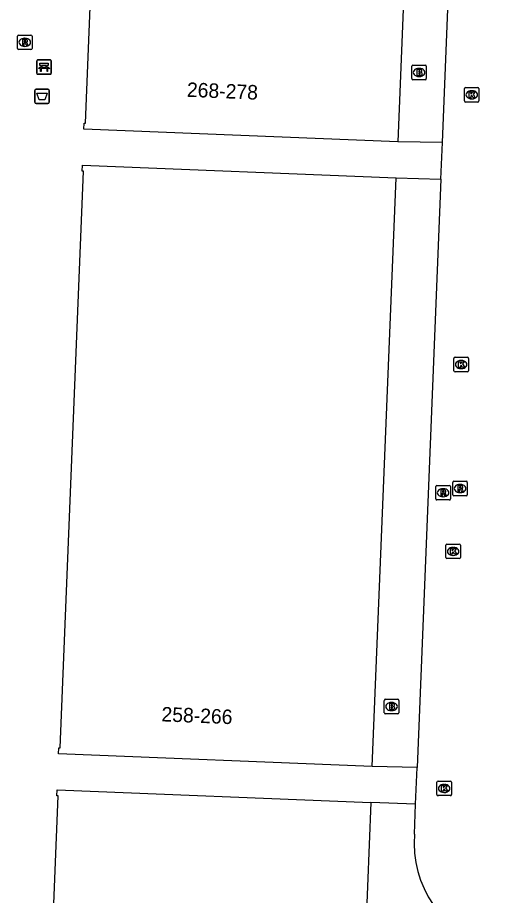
# Model space of a CAD drawing. Extents: x 160891 to 161384, y 386490 to 386907.
# Drawn here: x 161189.7 to 161223.2, y 386595.4 to 386656.1 of the extents above; entities that cross this region are included whole.
import ezdxf

# ---------------------------------------------------------------- set-up
doc = ezdxf.new("R2010")
doc.units = 0
for name, color, linetype in [('IMGEO_Afvalbak', 7, 'Continuous'), ('IMGEO_Bank', 7, 'Continuous'), ('IMGEO_Brandkraan', 7, 'Continuous'), ('IMGEO_Kolk', 7, 'Continuous'), ('IMGEO_Pand', 7, 'Continuous'), ('IMGEO_Pand_nummerreeks', 7, 'Continuous'), ('IMGEO_Rijbaan_lokaal_open', 7, 'Continuous'), ('IMGEO_Rioolput', 7, 'Continuous'), ('IMGEO_Voetgangersgebied_open', 7, 'Continuous'), ('IMGEO_Voetpad_open', 7, 'Continuous')]:
    doc.layers.add(name, color=color, linetype=linetype)

msp = doc.modelspace()

# ---------------------------------------------------------------- linework, layer by layer
at = {"layer": 'IMGEO_Afvalbak'}
for p, q in [((161190.919, 386650.214), (161190.919, 386651.014)), ((161190.919, 386651.014), (161190.919, 386650.214)), ((161191.019, 386651.114), (161191.809, 386651.114)), ((161191.809, 386651.114), (161191.019, 386651.114)), ((161191.909, 386651.014), (161191.909, 386650.214)), ((161191.909, 386650.214), (161191.909, 386651.014)), ((161191.809, 386650.114), (161191.019, 386650.114)), ((161191.019, 386650.114), (161191.809, 386650.114))]:
    msp.add_line(p, q, dxfattribs=at)
msp.add_lwpolyline([(161191.062, 386650.828), (161191.766, 386650.828), (161191.617, 386650.358), (161191.211, 386650.358), (161191.062, 386650.828)], dxfattribs=at)
for centre, start, end in [((161191.019, 386651.014), 90, 180), ((161191.019, 386651.014), 90, 180), ((161191.809, 386651.014), 0, 90), ((161191.809, 386651.014), 360, 90), ((161191.019, 386650.214), 180, 270), ((161191.019, 386650.214), 180, 270), ((161191.809, 386650.214), 270, 0), ((161191.809, 386650.214), 270, 0)]:
    msp.add_arc(centre, 0.1, start, end, dxfattribs=at)
at = {"layer": 'IMGEO_Bank'}
for p, q in [((161191.058, 386652.204), (161191.058, 386653.045)), ((161191.058, 386653.045), (161191.058, 386652.204)), ((161191.133, 386653.129), (161191.974, 386653.129)), ((161191.974, 386653.129), (161191.133, 386653.129)), ((161192.058, 386653.054), (161192.058, 386652.213)), ((161192.058, 386652.213), (161192.058, 386653.054)), ((161191.755, 386652.527), (161191.362, 386652.527)), ((161191.367, 386652.635), (161191.367, 386652.741)), ((161191.411, 386652.741), (161191.411, 386652.635)), ((161191.699, 386652.747), (161191.417, 386652.747)), ((161191.417, 386652.629), (161191.699, 386652.629)), ((161191.705, 386652.635), (161191.705, 386652.741)), ((161191.749, 386652.741), (161191.749, 386652.635)), ((161191.983, 386652.129), (161191.142, 386652.129)), ((161191.142, 386652.129), (161191.983, 386652.129))]:
    msp.add_line(p, q, dxfattribs=at)
for points in [[(161191.361, 386652.747), (161191.275, 386652.747), (161191.275, 386652.908), (161191.838, 386652.908), (161191.838, 386652.747), (161191.755, 386652.747)], [(161191.305, 386652.527), (161191.163, 386652.527), (161191.275, 386652.629), (161191.361, 386652.629)], [(161191.355, 386652.52), (161191.355, 386652.313), (161191.312, 386652.313), (161191.312, 386652.52)], [(161191.755, 386652.629), (161191.838, 386652.629), (161191.95, 386652.527), (161191.811, 386652.527)], [(161191.805, 386652.52), (161191.805, 386652.313), (161191.761, 386652.313), (161191.761, 386652.52)]]:
    msp.add_lwpolyline(points, dxfattribs=at)
for centre, radius, start, end in [((161191.136, 386653.051), 0.0779, 92.4484, 184.28452), ((161191.136, 386653.051), 0.0779, 92.4484, 184.28452), ((161191.98, 386653.051), 0.0779, 2.4484, 94.28452), ((161191.98, 386653.051), 0.0779, 2.4484, 94.28452), ((161191.136, 386652.207), 0.0779, 182.4484, 274.28452), ((161191.136, 386652.207), 0.0779, 182.4484, 274.28452), ((161191.305, 386652.52), 0.00671, 2.89567, 87.10433), ((161191.362, 386652.52), 0.00671, 92.89567, 177.10433), ((161191.36, 386652.74), 0.00671, 2.89567, 87.10433), ((161191.36, 386652.636), 0.00671, 272.89567, 357.10433), ((161191.417, 386652.74), 0.00671, 92.89567, 177.10433), ((161191.417, 386652.636), 0.00671, 182.89567, 267.10433), ((161191.699, 386652.74), 0.00671, 2.89567, 87.10433), ((161191.699, 386652.636), 0.00671, 272.89567, 357.10433), ((161191.756, 386652.74), 0.00671, 92.89567, 177.10433), ((161191.756, 386652.636), 0.00671, 182.89567, 267.10433), ((161191.754, 386652.52), 0.00671, 2.89567, 87.10433), ((161191.811, 386652.52), 0.00671, 92.89567, 177.10433), ((161191.98, 386652.207), 0.0779, 272.4484, 4.28452), ((161191.98, 386652.207), 0.0779, 272.4484, 4.28452)]:
    msp.add_arc(centre, radius, start, end, dxfattribs=at)
at = {"layer": 'IMGEO_Brandkraan'}
for p, q in [((161216.976, 386651.833), (161216.976, 386652.685)), ((161217.051, 386652.759), (161217.903, 386652.759)), ((161217.464, 386652.539), (161217.489, 386652.539)), ((161217.977, 386652.685), (161217.977, 386651.833)), ((161217.903, 386651.759), (161217.051, 386651.759)), ((161217.487, 386651.979), (161217.462, 386651.979)), ((161215.075, 386608.011), (161215.075, 386608.863)), ((161215.15, 386608.937), (161216.002, 386608.937)), ((161215.563, 386608.717), (161215.588, 386608.717)), ((161216.076, 386608.863), (161216.076, 386608.011)), ((161216.002, 386607.937), (161215.15, 386607.937)), ((161215.586, 386608.157), (161215.561, 386608.157))]:
    msp.add_line(p, q, dxfattribs=at)
for points in [[(161216.976, 386651.833), (161216.976, 386652.685)], [(161217.051, 386652.759), (161217.903, 386652.759)], [(161217.324, 386652.459), (161217.324, 386652.059), (161217.537, 386652.059)], [(161217.555, 386652.459), (161217.324, 386652.459)], [(161217.503, 386652.378), (161217.449, 386652.378), (161217.449, 386652.302)], [(161217.449, 386652.302), (161217.502, 386652.302)], [(161217.511, 386652.226), (161217.449, 386652.226), (161217.449, 386652.145)], [(161217.977, 386652.685), (161217.977, 386651.833)], [(161217.903, 386651.759), (161217.051, 386651.759)], [(161217.449, 386652.145), (161217.511, 386652.145)], [(161215.075, 386608.011), (161215.075, 386608.863)], [(161215.15, 386608.937), (161216.002, 386608.937)], [(161215.423, 386608.637), (161215.423, 386608.237), (161215.636, 386608.237)], [(161215.654, 386608.637), (161215.423, 386608.637)], [(161215.602, 386608.556), (161215.548, 386608.556), (161215.548, 386608.48)], [(161216.076, 386608.863), (161216.076, 386608.011)], [(161216.002, 386607.937), (161215.15, 386607.937)], [(161215.548, 386608.48), (161215.601, 386608.48)], [(161215.61, 386608.404), (161215.548, 386608.404), (161215.548, 386608.323)], [(161215.548, 386608.323), (161215.61, 386608.323)]]:
    msp.add_lwpolyline(points, dxfattribs=at)
for centre, radius, start, end in [((161217.053, 386652.683), 0.0765, 91.55205, 178.44795), ((161217.053, 386652.683), 0.0765, 91.55205, 178.44795), ((161217.504, 386652.34), 0.0379, 267.82845, 90.93552), ((161217.512, 386652.185), 0.0404, 269.87594, 90.50774), ((161217.559, 386652.314), 0.145, 59.4692, 91.53667), ((161217.584, 386652.361), 0.0922, 285.51372, 58.15012), ((161217.589, 386652.169), 0.105, 301.31148, 78.98903), ((161217.901, 386652.683), 0.0765, 1.55205, 88.44795), ((161217.901, 386652.683), 0.0765, 1.55205, 88.44795), ((161217.053, 386651.835), 0.0765, 181.55205, 268.44795), ((161217.053, 386651.835), 0.0765, 181.55205, 268.44795), ((161217.543, 386652.31), 0.251, 268.66757, 293.53466), ((161217.901, 386651.835), 0.0765, 271.55205, 358.44795), ((161217.901, 386651.835), 0.0765, 271.55205, 358.44795), ((161215.152, 386608.861), 0.0765, 91.55205, 178.44795), ((161215.152, 386608.861), 0.0765, 91.55205, 178.44795), ((161215.603, 386608.518), 0.0379, 267.82845, 90.93552), ((161215.658, 386608.492), 0.145, 59.4692, 91.53667), ((161215.683, 386608.539), 0.0922, 285.51372, 58.15012), ((161216, 386608.861), 0.0765, 1.55205, 88.44795), ((161216, 386608.861), 0.0765, 1.55205, 88.44795), ((161215.152, 386608.013), 0.0765, 181.55205, 268.44795), ((161215.152, 386608.013), 0.0765, 181.55205, 268.44795), ((161215.611, 386608.363), 0.0404, 269.87594, 90.50774), ((161215.642, 386608.488), 0.251, 268.66757, 293.53466), ((161215.688, 386608.347), 0.105, 301.31148, 78.98903), ((161216, 386608.013), 0.0765, 271.55205, 358.44795), ((161216, 386608.013), 0.0765, 271.55205, 358.44795)]:
    msp.add_arc(centre, radius, start, end, dxfattribs=at)
for centre, major_axis, ratio, start_param, end_param in [((161217.463, 386652.259), (-0.387, 0.002), 0.722429, 4.712389, 7.853982), ((161217.488, 386652.259), (-0.39, 0.002), 0.717154, 1.570796, 4.712389), ((161215.562, 386608.437), (-0.387, 0.002), 0.722429, 4.712389, 7.853982), ((161215.587, 386608.437), (-0.39, 0.002), 0.717154, 1.570796, 4.712389)]:
    msp.add_ellipse(centre, major_axis=major_axis, ratio=ratio, start_param=start_param, end_param=end_param, dxfattribs=at)
at = {"layer": 'IMGEO_Kolk'}
for p, q in [((161220.615, 386650.288), (161220.615, 386651.14)), ((161220.69, 386651.214), (161221.542, 386651.214)), ((161221.103, 386650.994), (161221.128, 386650.994)), ((161221.616, 386651.14), (161221.616, 386650.288)), ((161221.126, 386650.434), (161221.101, 386650.434)), ((161221.542, 386650.214), (161220.69, 386650.214)), ((161219.886, 386631.645), (161219.886, 386632.497)), ((161219.961, 386632.571), (161220.813, 386632.571)), ((161220.374, 386632.351), (161220.399, 386632.351)), ((161220.887, 386632.497), (161220.887, 386631.645)), ((161220.813, 386631.571), (161219.961, 386631.571)), ((161220.397, 386631.791), (161220.372, 386631.791)), ((161219.331, 386618.732), (161219.331, 386619.584)), ((161219.406, 386619.658), (161220.258, 386619.658)), ((161219.819, 386619.438), (161219.844, 386619.438)), ((161220.332, 386619.584), (161220.332, 386618.732)), ((161219.842, 386618.878), (161219.817, 386618.878)), ((161220.258, 386618.658), (161219.406, 386618.658)), ((161218.71, 386602.352), (161218.71, 386603.204)), ((161218.785, 386603.278), (161219.637, 386603.278)), ((161219.198, 386603.058), (161219.223, 386603.058)), ((161219.711, 386603.204), (161219.711, 386602.352)), ((161219.221, 386602.498), (161219.196, 386602.498)), ((161219.637, 386602.278), (161218.785, 386602.278))]:
    msp.add_line(p, q, dxfattribs=at)
for points in [[(161220.615, 386650.288), (161220.615, 386651.14)], [(161220.69, 386651.214), (161221.542, 386651.214)], [(161221.616, 386651.14), (161221.616, 386650.288)], [(161220.936, 386650.914), (161221.059, 386650.914), (161221.059, 386650.763), (161221.189, 386650.914), (161221.353, 386650.914), (161221.207, 386650.763), (161221.36, 386650.514), (161221.208, 386650.514), (161221.123, 386650.678), (161221.059, 386650.611), (161221.059, 386650.514), (161220.936, 386650.514), (161220.936, 386650.914)], [(161221.542, 386650.214), (161220.69, 386650.214)], [(161219.886, 386631.645), (161219.886, 386632.497)], [(161219.961, 386632.571), (161220.813, 386632.571)], [(161220.207, 386632.271), (161220.33, 386632.271), (161220.33, 386632.12), (161220.46, 386632.271), (161220.624, 386632.271), (161220.478, 386632.12), (161220.631, 386631.871), (161220.479, 386631.871), (161220.394, 386632.035), (161220.33, 386631.968), (161220.33, 386631.871), (161220.207, 386631.871), (161220.207, 386632.271)], [(161220.887, 386632.497), (161220.887, 386631.645)], [(161220.813, 386631.571), (161219.961, 386631.571)], [(161219.331, 386618.732), (161219.331, 386619.584)], [(161219.406, 386619.658), (161220.258, 386619.658)], [(161220.332, 386619.584), (161220.332, 386618.732)], [(161219.652, 386619.358), (161219.775, 386619.358), (161219.775, 386619.207), (161219.905, 386619.358), (161220.069, 386619.358), (161219.923, 386619.207), (161220.076, 386618.958), (161219.924, 386618.958), (161219.839, 386619.122), (161219.775, 386619.055), (161219.775, 386618.958), (161219.652, 386618.958), (161219.652, 386619.358)], [(161220.258, 386618.658), (161219.406, 386618.658)], [(161218.71, 386602.352), (161218.71, 386603.204)], [(161218.785, 386603.278), (161219.637, 386603.278)], [(161219.711, 386603.204), (161219.711, 386602.352)], [(161219.031, 386602.978), (161219.154, 386602.978), (161219.154, 386602.827), (161219.284, 386602.978), (161219.448, 386602.978), (161219.302, 386602.827), (161219.455, 386602.578), (161219.303, 386602.578), (161219.218, 386602.742), (161219.154, 386602.675), (161219.154, 386602.578), (161219.031, 386602.578), (161219.031, 386602.978)], [(161219.637, 386602.278), (161218.785, 386602.278)]]:
    msp.add_lwpolyline(points, dxfattribs=at)
for centre, start, end in [((161220.692, 386651.138), 91.55205, 178.44795), ((161220.692, 386651.138), 91.55205, 178.44795), ((161221.54, 386651.138), 1.55205, 88.44795), ((161221.54, 386651.138), 1.55205, 88.44795), ((161220.692, 386650.29), 181.55205, 268.44795), ((161220.692, 386650.29), 181.55205, 268.44795), ((161221.54, 386650.29), 271.55205, 358.44795), ((161221.54, 386650.29), 271.55205, 358.44795), ((161219.963, 386632.495), 91.55205, 178.44795), ((161219.963, 386632.495), 91.55205, 178.44795), ((161220.811, 386632.495), 1.55205, 88.44795), ((161220.811, 386632.495), 1.55205, 88.44795), ((161219.963, 386631.647), 181.55205, 268.44795), ((161219.963, 386631.647), 181.55205, 268.44795), ((161220.811, 386631.647), 271.55205, 358.44795), ((161220.811, 386631.647), 271.55205, 358.44795), ((161219.408, 386619.582), 91.55205, 178.44795), ((161219.408, 386619.582), 91.55205, 178.44795), ((161220.256, 386619.582), 1.55205, 88.44795), ((161220.256, 386619.582), 1.55205, 88.44795), ((161219.408, 386618.734), 181.55205, 268.44795), ((161219.408, 386618.734), 181.55205, 268.44795), ((161220.256, 386618.734), 271.55205, 358.44795), ((161220.256, 386618.734), 271.55205, 358.44795), ((161218.787, 386603.202), 91.55205, 178.44795), ((161218.787, 386603.202), 91.55205, 178.44795), ((161219.635, 386603.202), 1.55205, 88.44795), ((161219.635, 386603.202), 1.55205, 88.44795), ((161218.787, 386602.354), 181.55205, 268.44795), ((161218.787, 386602.354), 181.55205, 268.44795), ((161219.635, 386602.354), 271.55205, 358.44795), ((161219.635, 386602.354), 271.55205, 358.44795)]:
    msp.add_arc(centre, 0.0765, start, end, dxfattribs=at)
for centre, major_axis, ratio, start_param, end_param in [((161221.102, 386650.714), (-0.387, 0.002), 0.722429, 4.712389, 7.853982), ((161221.127, 386650.714), (-0.39, 0.002), 0.717154, 1.570796, 4.712389), ((161220.373, 386632.071), (-0.387, 0.002), 0.722429, 4.712389, 7.853982), ((161220.398, 386632.071), (-0.39, 0.002), 0.717154, 1.570796, 4.712389), ((161219.818, 386619.158), (-0.387, 0.002), 0.722429, 4.712389, 7.853982), ((161219.843, 386619.158), (-0.39, 0.002), 0.717154, 1.570796, 4.712389), ((161219.197, 386602.778), (-0.387, 0.002), 0.722429, 4.712389, 7.853982), ((161219.222, 386602.778), (-0.39, 0.002), 0.717154, 1.570796, 4.712389)]:
    msp.add_ellipse(centre, major_axis=major_axis, ratio=ratio, start_param=start_param, end_param=end_param, dxfattribs=at)
at = {"layer": 'IMGEO_Pand'}
for points in [[(161216.005, 386647.458), (161194.302, 386648.347), (161194.32, 386648.757), (161194.42, 386648.752), (161196.801, 386707.775)], [(161214.777, 386707.152), (161234.482, 386694.929), (161234.896, 386694.91), (161234.274, 386679.434), (161217.32, 386680.124), (161216.005, 386647.458)], [(161214.242, 386604.304), (161192.56, 386605.179), (161192.572, 386605.592), (161192.672, 386605.589), (161194.288, 386645.43), (161194.188, 386645.434), (161194.205, 386645.849), (161215.889, 386644.972)], [(161214.242, 386604.304), (161215.889, 386644.972)], [(161191.198, 386569.006), (161192.541, 386602.265), (161192.441, 386602.269), (161192.456, 386602.678), (161214.141, 386601.806)], [(161214.141, 386601.806), (161213.556, 386587.296)]]:
    msp.add_lwpolyline(points, dxfattribs=at)
at = {"layer": 'IMGEO_Rijbaan_lokaal_open'}
for points in [[(161219.091, 386647.411), (161219.977, 386669.302)], [(161218.989, 386644.89), (161219.091, 386647.411)], [(161218.989, 386644.89), (161217.342, 386604.22)], [(161217.24, 386601.701), (161217.342, 386604.22)], [(161217.156, 386599.626), (161217.24, 386601.701)]]:
    msp.add_lwpolyline(points, dxfattribs=at)
msp.add_arc((161224.629, 386599.004), 7.499, 175.24232, 253.73554, dxfattribs=at)
at = {"layer": 'IMGEO_Rioolput'}
for p, q in [((161189.724, 386653.917), (161189.724, 386654.769)), ((161189.799, 386654.843), (161190.651, 386654.843)), ((161190.212, 386654.623), (161190.237, 386654.623)), ((161190.725, 386654.769), (161190.725, 386653.917)), ((161190.235, 386654.063), (161190.21, 386654.063)), ((161190.651, 386653.843), (161189.799, 386653.843)), ((161218.711, 386623.712), (161219.563, 386623.712)), ((161219.81, 386623.079), (161219.81, 386623.931)), ((161219.885, 386624.005), (161220.737, 386624.005)), ((161220.298, 386623.785), (161220.323, 386623.785)), ((161220.811, 386623.931), (161220.811, 386623.079)), ((161218.636, 386622.786), (161218.636, 386623.638)), ((161219.124, 386623.492), (161219.149, 386623.492)), ((161219.637, 386623.638), (161219.637, 386622.786)), ((161220.321, 386623.225), (161220.296, 386623.225)), ((161219.563, 386622.712), (161218.711, 386622.712)), ((161219.147, 386622.932), (161219.122, 386622.932)), ((161220.737, 386623.005), (161219.885, 386623.005))]:
    msp.add_line(p, q, dxfattribs=at)
for points in [[(161189.724, 386653.917), (161189.724, 386654.769)], [(161189.799, 386654.843), (161190.651, 386654.843)], [(161190.725, 386654.769), (161190.725, 386653.917)], [(161190.313, 386654.541), (161190.061, 386654.543), (161190.061, 386654.143)], [(161190.061, 386654.143), (161190.185, 386654.143), (161190.185, 386654.305), (161190.196, 386654.305)], [(161190.239, 386654.462), (161190.185, 386654.462), (161190.185, 386654.381)], [(161190.185, 386654.381), (161190.237, 386654.381)], [(161190.243, 386654.276), (161190.314, 386654.143), (161190.454, 386654.143), (161190.389, 386654.269)], [(161190.651, 386653.843), (161189.799, 386653.843)], [(161218.711, 386623.712), (161219.563, 386623.712)], [(161219.81, 386623.079), (161219.81, 386623.931)], [(161219.885, 386624.005), (161220.737, 386624.005)], [(161220.399, 386623.703), (161220.147, 386623.705), (161220.147, 386623.305)], [(161220.811, 386623.931), (161220.811, 386623.079)], [(161218.636, 386622.786), (161218.636, 386623.638)], [(161219.225, 386623.41), (161218.973, 386623.412), (161218.973, 386623.012)], [(161218.973, 386623.012), (161219.097, 386623.012), (161219.097, 386623.174), (161219.108, 386623.174)], [(161219.151, 386623.331), (161219.097, 386623.331), (161219.097, 386623.25)], [(161219.097, 386623.25), (161219.149, 386623.25)], [(161219.155, 386623.145), (161219.226, 386623.012), (161219.366, 386623.012), (161219.301, 386623.138)], [(161219.637, 386623.638), (161219.637, 386622.786)], [(161220.147, 386623.305), (161220.271, 386623.305), (161220.271, 386623.467), (161220.282, 386623.467)], [(161220.325, 386623.624), (161220.271, 386623.624), (161220.271, 386623.543)], [(161220.271, 386623.543), (161220.323, 386623.543)], [(161220.329, 386623.438), (161220.4, 386623.305), (161220.54, 386623.305), (161220.475, 386623.431)], [(161219.563, 386622.712), (161218.711, 386622.712)], [(161220.737, 386623.005), (161219.885, 386623.005)]]:
    msp.add_lwpolyline(points, dxfattribs=at)
for centre, radius, start, end in [((161189.801, 386654.767), 0.0765, 91.55205, 178.44795), ((161189.801, 386654.767), 0.0765, 91.55205, 178.44795), ((161190.649, 386654.767), 0.0765, 1.55205, 88.44795), ((161190.649, 386654.767), 0.0765, 1.55205, 88.44795), ((161190.195, 386654.252), 0.0533, 26.02933, 88.69889), ((161190.221, 386654.57), 0.19, 274.7715, 282.96867), ((161190.245, 386654.366), 0.0964, 77.00612, 93.18647), ((161190.259, 386654.423), 0.0378, 276.66336, 79.67722), ((161190.312, 386654.431), 0.109, 350.36119, 89.41601), ((161190.31, 386654.431), 0.112, 277.58423, 350.98172), ((161190.294, 386654.216), 0.108, 29.51342, 73.79051), ((161189.801, 386653.919), 0.0765, 181.55205, 268.44795), ((161189.801, 386653.919), 0.0765, 181.55205, 268.44795), ((161190.649, 386653.919), 0.0765, 271.55205, 358.44795), ((161190.649, 386653.919), 0.0765, 271.55205, 358.44795), ((161218.713, 386623.636), 0.0765, 91.55205, 178.44795), ((161218.713, 386623.636), 0.0765, 91.55205, 178.44795), ((161219.561, 386623.636), 0.0765, 1.55205, 88.44795), ((161219.561, 386623.636), 0.0765, 1.55205, 88.44795), ((161219.887, 386623.929), 0.0765, 91.55205, 178.44795), ((161219.887, 386623.929), 0.0765, 91.55205, 178.44795), ((161220.398, 386623.593), 0.109, 350.36119, 89.41601), ((161220.735, 386623.929), 0.0765, 1.55205, 88.44795), ((161220.735, 386623.929), 0.0765, 1.55205, 88.44795), ((161219.107, 386623.121), 0.0533, 26.02933, 88.69889), ((161219.133, 386623.439), 0.19, 274.7715, 282.96867), ((161219.157, 386623.235), 0.0964, 77.00612, 93.18647), ((161219.171, 386623.292), 0.0378, 276.66336, 79.67722), ((161219.224, 386623.3), 0.109, 350.36119, 89.41601), ((161219.222, 386623.3), 0.112, 277.58423, 350.98172), ((161219.206, 386623.085), 0.108, 29.51342, 73.79051), ((161219.887, 386623.081), 0.0765, 181.55205, 268.44795), ((161219.887, 386623.081), 0.0765, 181.55205, 268.44795), ((161220.281, 386623.414), 0.0533, 26.02933, 88.69889), ((161220.307, 386623.732), 0.19, 274.7715, 282.96867), ((161220.331, 386623.528), 0.0964, 77.00612, 93.18647), ((161220.345, 386623.585), 0.0378, 276.66336, 79.67722), ((161220.396, 386623.593), 0.112, 277.58423, 350.98172), ((161220.38, 386623.378), 0.108, 29.51342, 73.79051), ((161220.735, 386623.081), 0.0765, 271.55205, 358.44795), ((161220.735, 386623.081), 0.0765, 271.55205, 358.44795), ((161218.713, 386622.788), 0.0765, 181.55205, 268.44795), ((161218.713, 386622.788), 0.0765, 181.55205, 268.44795), ((161219.561, 386622.788), 0.0765, 271.55205, 358.44795), ((161219.561, 386622.788), 0.0765, 271.55205, 358.44795)]:
    msp.add_arc(centre, radius, start, end, dxfattribs=at)
for centre, major_axis, ratio, start_param, end_param in [((161190.211, 386654.343), (-0.387, 0.002), 0.722429, 4.712389, 7.853982), ((161190.236, 386654.343), (-0.39, 0.002), 0.717154, 1.570796, 4.712389), ((161220.297, 386623.505), (-0.387, 0.002), 0.722429, 4.712389, 7.853982), ((161220.322, 386623.505), (-0.39, 0.002), 0.717154, 1.570796, 4.712389), ((161219.123, 386623.212), (-0.387, 0.002), 0.722429, 4.712389, 7.853982), ((161219.148, 386623.212), (-0.39, 0.002), 0.717154, 1.570796, 4.712389)]:
    msp.add_ellipse(centre, major_axis=major_axis, ratio=ratio, start_param=start_param, end_param=end_param, dxfattribs=at)
at = {"layer": 'IMGEO_Voetgangersgebied_open'}
msp.add_lwpolyline([(161219.091, 386647.411), (161216.005, 386647.458)], dxfattribs=at)
at = {"layer": 'IMGEO_Voetpad_open'}
for points in [[(161215.889, 386644.972), (161218.989, 386644.89)], [(161217.342, 386604.22), (161214.242, 386604.304)], [(161217.24, 386601.701), (161214.141, 386601.806)]]:
    msp.add_lwpolyline(points, dxfattribs=at)

# ---------------------------------------------------------------- texts
at = {"layer": 'IMGEO_Pand_nummerreeks'}
for s, rotation, p in [('268-278', 357.65436, (161201.414, 386650.578)), ('258-266', 357.68902, (161199.656, 386607.415))]:
    msp.add_text(s, height=1, rotation=rotation, dxfattribs=at).set_placement(p)

doc.saveas('drawing.dxf')
